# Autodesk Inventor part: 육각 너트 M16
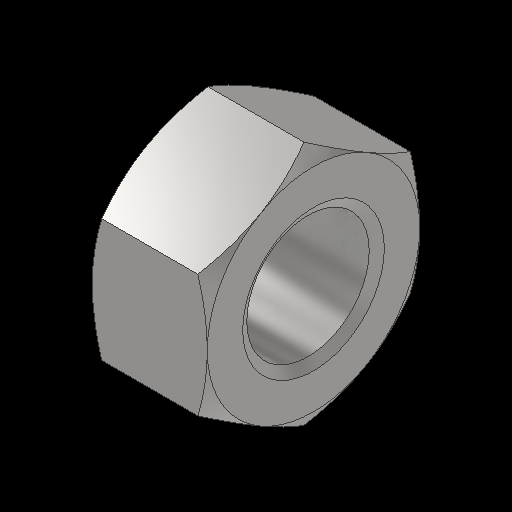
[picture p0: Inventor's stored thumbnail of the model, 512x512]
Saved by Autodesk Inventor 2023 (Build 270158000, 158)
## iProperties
Created: 2025-01
Part Number: 육각 너트 M16
Material: 강철, 연강
Description: 6각 너트
Document SubType Name: Modeling
Designer: 강의실01
Density: 7.85 g/cm^3
Appearance: 기본값
Author: jhkim
Sending System: Autodesk Inventor 2025
Preprocessor: ST-DEVELOPER v20
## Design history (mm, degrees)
feature "Solid1"
node "솔리드1"
